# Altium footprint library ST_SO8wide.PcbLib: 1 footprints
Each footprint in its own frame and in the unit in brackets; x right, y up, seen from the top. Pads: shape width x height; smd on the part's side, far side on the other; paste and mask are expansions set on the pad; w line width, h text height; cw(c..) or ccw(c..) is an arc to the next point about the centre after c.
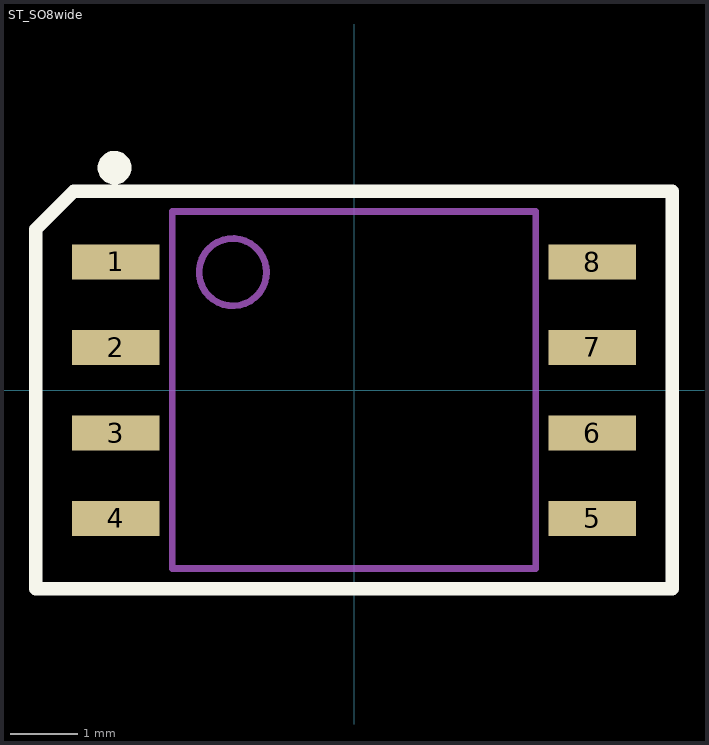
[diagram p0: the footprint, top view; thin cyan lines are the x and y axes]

## ST_SO8wide [mm] "ST_SO8wide"
height 2.1
pads (8):
  rect 1.3x0.52 smd: 1(-3.54,1.905) 2(-3.54,0.635) 3(-3.54,-0.635) 4(-3.54,-1.905) 5(3.54,-1.905) 6(3.54,-0.635) 7(3.54,0.635) 8(3.54,1.905)
Top Overlay:
  circle w0.25: c-3.556,3.302 r0.125
  lines w0.2: -4.725,-2.95 4.725,-2.95 4.725,2.95 -4.162,2.95 -4.725,2.387 -4.725,-2.95
Mechanical 13:
  circle w0.1: c-1.8,1.75 r0.5
  lines w0.1: -2.7,-2.65 -2.7,2.65 2.7,2.65 2.7,-2.65 -2.7,-2.65
3D body "ST_SO8wide.step": height 2.1, standoff 0, extent -3.988,-2.65 3.988,2.65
